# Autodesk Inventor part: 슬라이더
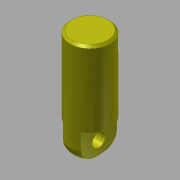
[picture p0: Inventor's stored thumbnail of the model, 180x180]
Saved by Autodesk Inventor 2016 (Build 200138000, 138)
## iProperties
Created: 2016-08
Part Number: 슬라이더
Material: 강철, 탄소
Document SubType Name: Modeling
Designer: mduedu
Density: 7.87 g/cm^3
Appearance: 노란색
Author: mduedu
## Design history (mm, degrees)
sketch "스케치1"
  geometry: C1 r 9 at (0, 0); 1 further point
  constraints: 1 centre point, 1 coincident
  dimensions: "d0" = 18 diameter of C1
extrude "돌출1" new body sketch "스케치1" distance "d1" = 47; taper "d2" = 0 deg
fillet "모깎기1" dims "d21" = 6
sketch "스케치6"
  geometry: L1 (9, 6)-(9, 47) reference; L2 (-9, 6)-(-9, 47) reference; L3 (9, 47)-(-9, 47) reference; L4 (0, 47)-(0, 0); L5 (9, 13)-(4, 13); L6 (4, 13)-(4, 0); L7 (4, 0)-(9, 0); L8 (9, 0)-(9, 13); L9 (-9, 13)-(-4, 13); L10 (-4, 13)-(-4, 0); L11 (-4, 0)-(-9, 0); L12 (-9, 0)-(-9, 13)
  constraints: 18 end point, 4 symmetric about line, 2 parallel, 2 perpendicular, 1 horizontal, 1 horizontal alignment, 1 midpoint, 1 point on line
  dimensions: "d22" = 13 distance of L7.end L5.start; "d24" = 4 distance between parallel lines of L6 L4
extrude "돌출5" cut sketch "스케치6" stored distance "d25" = 8; taper "d26" = 0 deg
sketch "스케치8"
  geometry: C1 r 3 at (6, 0); 1 further point
  constraints: 1 centre point, 1 horizontal alignment
  dimensions: "d27" = 6 diameter of C1; "d28" = 6 distance of point (0, 0) C1.centre
extrude "돌출6" cut sketch "스케치8" stored distance "d29" = 8; taper "d30" = 0 deg
chamfer "모따기2" distance "d43" = 1; stored, may be unused: second distance "d44" = 2, angle "d45" = 30 deg
node "솔리드1"
